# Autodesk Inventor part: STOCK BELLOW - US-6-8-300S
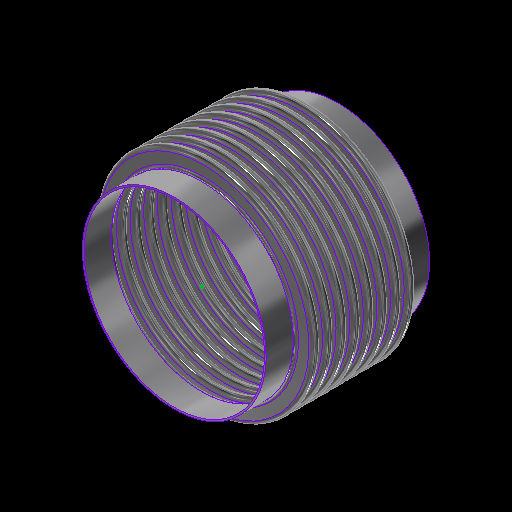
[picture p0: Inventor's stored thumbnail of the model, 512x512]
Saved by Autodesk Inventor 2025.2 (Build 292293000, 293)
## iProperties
Category: 22 GA (0.030 THICK)
RuleStatus: InUse
Created: 2024-01
Part Number: STOCK BELLOW - US-6-8-300S
Project: =STOCK BELLOWS: <Stock Number><SFILL>
Material: ASTM A240-304
Description: =STOCK BELLOWS: <Stock Number>, <SID_> I.D., <SOD_> O.D., <SPLY_> PLY, <Category>, <SNET_CONS> CONS.<PITCH_><STANGENT_> TANGENT<SFILL>
Document SubType Name: Sheet Metal
Designer: GS
Stock Number: U.S-6-8-300S
Surface Area: 4243.64 cm^2
Volume: 319.648 cm^3
Sheet Metal Rule: Default
Appearance: STAINLESS STEEL
Mass: 2575.5 g
Density: 8.05729 g/cm^3
THK: 0.036
ID: 3.500
OD: 4.250
CONS_: 2
PITCH: 0.500
TANGENT: 0.500
BELLOWS_UPSET: 0.000
d79: 1.000
d82: 1.000
d83: 26.000
d84: 24.000
d174: 8
d214: 8
STHK_: 0.030
SID_: 6.625
SOD_: 8.000
SPITCH_: 0.500
STANGENT__: 1.000
SBELLOWS_UPSET_: 0.000
SDIFF_TAN: 1.000
d252: 2
d275: 2
d287: 0.050
d289: 0.500
d290: 0.000
SOD_NECK: 6 3/4
PLY: 1
PSET: 4.178
PBAR: 1.035
COUNTER: 1.500
NET_TUBE: 3.071
CONS: 2
S_CONS: 0
NET_CONS: 2
ID_M: 88.90 mm
OD_M: 107.95 mm
THK_M: 0.91 mm
ID_U: 3.500 in
OD_U: 4.250 in
THK_U: 0.036 in
TANGENT2: 0.500
TAN_TO_TAN: 1.000 in
d80: 2.571
d81: 10
SID: 2.375
SCONS_: 8
SPITCH: 0.250
STANGENT_: 1.000
SBELLOWS_UPSET: 0.000
SNET_CONS: 8
SS_CONS: 0
SCONS: 8
d190: 8
d191: 1
d192: 1
d193: 8
d194: 0
SIZE: 6.00
PRESSURE: 300
d230: 8
STANGENT: 4.000
SPLY_: 2
d233: 8
d234: 0
d263: 2
d265: 1
d268: 2
d269: 0
d286: 2
d288: 1
d291: 2
d292: 0
SREROLL: 0.750
BLETP: 0.000 ul
PRES_Copy: 85
MATTABLE: 20 GA (0.036 THICK)
PART_NUMBER: U.S-6-8-300S
PITCH_: =, <SPITCH_> PITCH,
CFILL: .
SFILL: .
MESH: ,
COMP: 0.84
EXT: 0.42
LAT: 0.15
ANG: 573
ASR: 2809
LSR: 14080
ANSR: 328
PRES: 300
COMPM: 8.4
EXTM: 4.2
LATM: 1.50
ASRM: 491.940
PRESM: 20.684
LSRM: 2465.830
ANSRM: 57.443
TEMPMIN: 20
TEMPMAX: 800
TEMPMINM: -7
TEMPMAXM: 427
WEIGHTM: 2.575
WEIGHT: 5.678
Author: GS
Keywords: 20 GA (0.036 THICK)
Comments: =STOCK BELLOW - <STOCK NUMBER>
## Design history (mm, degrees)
sketch "Sketch2"
  geometry: L1 (0, -177.245)-(0, 562.856) reference; L2 (45.364, 0)-(44.45, 0); L3 (48.082, -2.718)-(50.343, -2.718); L4 (48.082, -3.632)-(50.343, -3.632); L5 (50.343, -9.982)-(48.082, -9.982); L6 (50.343, -9.068)-(48.082, -9.068); L7 (45.364, -12.7)-(44.45, -12.7); L8 (48.082, 0)-(48.082, -12.7); L9 (50.343, -6.35)-(53.975, -6.35); L10 (44.45, 0)-(44.45, -12.7); L11 (20.376, 102.841)-(20.376, 101.926); L12 (58.262, 457.127)-(58.262, 349.177); L13 (58.262, 444.427)-(58.262, 336.477); L14 (93.133, -58.817)-(93.133, -71.517); L15 (118.746, -66.401)-(118.746, -66.401); L16 (50.343, -9.068)-(50.343, -9.982); L17 (48.082, -9.068)-(48.082, -9.982); L18 (48.082, -9.525)-(50.343, -9.525); L19 (53.975, 0)-(53.975, -12.7); L20 (-50.343, -9.068)-(-50.343, -9.982); L21 (-50.343, -2.718)-(-48.082, -2.718); L22 (-50.343, -3.632)-(-48.082, -3.632); L23 (-48.082, -9.068)-(-50.343, -9.068); L24 (-50.343, -9.525)-(-48.082, -9.525); L25 (-48.082, -9.982)-(-50.343, -9.982); L26 (-48.082, -9.068)-(-48.082, -9.982); L27 (-44.45, 0.653)-(-44.45, -12.047); L28 (-48.082, -6.35)-(-44.45, -6.35); L29 (-50.343, 0.653)-(-50.343, -12.7); L30 (-53.061, 0)-(-53.975, 0); L31 (-53.975, 0)-(-53.975, -12.7); L32 (-53.061, -12.7)-(-53.975, -12.7); A1 r 2.718 centre (48.082, 0) between (45.364, 0) and (48.082, -2.718); A2 r 3.632 centre (48.082, 0) between (44.45, 0) and (48.082, -3.632); A3 r 3.632 centre (50.343, -6.35) between (50.343, -9.982) and (50.343, -2.718); A4 r 2.718 centre (50.343, -6.35) between (50.343, -9.068) and (50.343, -3.632); A5 r 2.718 centre (48.082, -12.7) between (48.082, -9.982) and (45.364, -12.7); A6 r 3.632 centre (48.082, -12.7) between (48.082, -9.068) and (44.45, -12.7); A7 r 3.175 centre (50.343, -6.35) between (50.343, -9.525) and (53.518, -6.35); A8 r 3.175 centre (48.082, -12.7) between (48.082, -9.525) and (44.907, -12.7); A9 r 2.718 centre (-50.343, -12.7) between (-50.343, -9.982) and (-53.061, -12.7); A10 r 2.718 centre (-48.082, -6.35) between (-48.082, -9.068) and (-48.082, -3.632); A11 r 3.175 centre (-48.082, -6.35) between (-48.082, -9.525) and (-44.907, -6.35); A12 r 3.632 centre (-48.082, -6.35) between (-48.082, -9.982) and (-48.082, -2.718); A13 r 3.175 centre (-50.343, -12.7) between (-50.343, -9.525) and (-53.518, -12.7); A14 r 3.632 centre (-50.343, -12.7) between (-50.343, -9.068) and (-53.975, -12.7); A15 r 2.718 centre (-50.343, 0) between (-53.061, 0) and (-50.343, -2.718); A16 r 3.632 centre (-50.343, 0) between (-53.975, 0) and (-50.343, -3.632); 10 further points
  constraints: 62 end point, 38 point on circle, 20 tangent, 16 centre point, 12 parallel, 9 midpoint, 7 vertical, 6 coincident, 6 concentric, 6 point on line, 4 equal radius, 4 perpendicular, 3 horizontal, 1 collinear, 1 horizontal alignment, 10 other
  dimensions: "THK" = 0.9144 distance of L11.start L11.end; "ID" = 88.9 distance of L11.end point (20.376, 13.026); "OD" = 107.95 distance of L12.start L12.end; "PITCH" = 12.7 distance of L12.start L13.start; "TANGENT" = 12.7 distance of L14.start L14.end; "BELLOWS_UPSET" = 0 distance of L15.start L15.end; "d43" = 88.9 diameter of L10 L1 (= ID); "d44" = 107.95 diameter of L9.end L1 (= OD); "d45" = 0.9144 distance between parallel lines of L5 L6 (computed from THK, PLY); "d46" = 3.6322 radius of A3 (computed from PITCH, THK, PLY); "UPSET_PITCH" = 12.7 distance of L2.end L7.end (derived); "SIDEWALL_ANGLE" = 360 deg dimension on L3 L9 (derived); "CON_GAP" = 5.4356 distance of point (48.082, -9.068) point (48.082, -3.632) (derived); "TAN1" = 4.98728 dimension on A8 (derived); "TAN2" = 4.98728 dimension on A7 (derived); "LEG1" = 2.2606 distance of L18.start L18.end (derived); "d278" = 0.9144 distance between parallel lines of L25 L23 (derived); "d279" = 3.6322 radius of A12 (derived); "d280" = 12.7 distance of L30.end L31.end (derived); "d281" = 360 deg dimension on L21 L28 (derived); "d282" = 5.4356 distance of point (-50.343, -9.068) point (-50.343, -3.632) (derived); "d283" = 4.98728 dimension on A13 (derived); "d284" = 4.98728 dimension on A11 (derived); "d285" = 2.2606 distance of L24.start L24.end (derived); "d293" = 88.9 diameter of L27 L1 (derived); "d294" = 107.95 diameter of L31 L1 (derived)
  node "Sketch Rectangular Pattern1" dims "d31" = 25.4, "ID" = 88.9
  node "Sketch Rectangular Pattern2" dims "d39" = 25.4, "PITCH" = 12.7
revolve "CONS" stored, may be unused: angle "d48" = 90 deg
node "BELLOW MIDPLANE"
pattern_linear "Rectangular Pattern2" dims "d52" = 12.7 (= UPSET_PITCH)
sketch "Sketch5"
  geometry: C1 r 45.364 at (0, 0) reference; C2 r 44.45 at (0, 0) reference
extrude "TANGENT" new body sketch "Sketch5" distance "d53" = 12.7 (= TANGENT); taper "d54" = 0 deg
revolve "SAMETAN" stored, may be unused: angle "d65" = 90 deg
revolve "DIFFTAN" stored, may be unused: angle "d70" = 90 deg
sketch "Sketch9"
  geometry: L1 (53.319, 0)-(-53.319, 0) reference; L2 (0, -17.78)-(0, 17.78) reference; L3 (38.085, 0)-(-38.085, 0); L4 (38.085, -11.906)-(38.085, 11.906); L5 (25.385, -11.906)-(25.385, 11.906); L6 (13.15, 11.906)-(13.15, -11.906); L7 (-25.385, -11.906)-(-25.385, 11.906); L8 (-38.085, -11.906)-(-38.085, 11.906); L9 (37.291, -11.906)-(37.291, 11.906); L10 (38.085, -11.906)-(37.291, -11.906); L11 (38.085, 11.906)-(37.291, 11.906); L12 (13.546, 11.906)-(12.753, 11.906); L13 (12.753, 11.906)-(12.753, -11.906); L14 (12.753, -11.906)-(13.546, -11.906); L15 (13.546, -11.906)-(13.546, 11.906); L16 (-13.546, 11.906)-(-13.546, -11.906); L17 (-13.15, 11.906)-(-13.15, -11.906); L18 (-13.546, -11.906)-(-12.753, -11.906); L19 (-12.753, -11.906)-(-12.753, 11.906); L20 (-12.753, 11.906)-(-13.546, 11.906); L21 (-38.085, -11.906)-(-37.291, -11.906); L22 (-37.291, -11.906)-(-37.291, 11.906); L23 (-37.291, 11.906)-(-38.085, 11.906); L24 (-38.085, 11.906)-(-38.085, -11.906); L25 (38.085, -0.397)-(-38.085, -0.397); L26 (-38.085, -0.397)-(-38.085, 0.397); L27 (-38.085, 0.397)-(38.085, 0.397); L28 (38.085, 0.397)-(38.085, -0.397); L29 (-38.085, 11.906)-(38.085, 11.906); L30 (38.085, 11.906)-(38.085, 12.7); L31 (38.085, 12.7)-(-38.085, 12.7); L32 (-38.085, 12.7)-(-38.085, 11.906); L33 (38.085, -11.906)-(-38.085, -11.906); L34 (-38.085, -11.906)-(-38.085, -12.7); L35 (-38.085, -12.7)-(38.085, -12.7); L36 (38.085, -12.7)-(38.085, -11.906); 30 further points
  constraints: 68 end point, 13 midpoint, 13 parallel, 8 horizontal, 7 perpendicular, 6 equal length, 3 point on line, 2 vertical, 14 other
  dimensions: "d115" = 23.8125 distance of L4.start L4.end (derived); "d116" = 12.7 distance between parallel lines of L4 L5 (derived); "d117" = 12.23516 distance between parallel lines of L5 L6 (derived); "d125" = 38.53427 distance between parallel lines of L7 L6 (derived); "d127" = 12.7 distance between parallel lines of L8 L7 (derived); "d128" = 24.93516 distance between parallel lines of L6 L4 (derived); "d130" = 76.16943 distance between parallel lines of L8 L4 (derived); "RULER_THK" = 0.79375 distance between parallel lines of L4 L9; "d135" = 0.79375 distance of L13.end L14.end (derived); "d138" = 26.29911 distance of L13.end L16.end (derived); "d143" = 0.79375 distance of L22.end L8.end (derived); "d144" = 0.79375 distance between parallel lines of L27 L25 (derived)
extrude "RULER" join sketch "Sketch9" distance "d149" = 0.79375 (derived); taper "d150" = 0 deg
extrude "BARS" join sketch "Sketch9" distance "d151" = 0.79375 (derived); taper "d152" = 0 deg
pattern_linear "Rectangular Pattern4" dims "d155" = 26.29911 (derived)
sketch "Sketch13"
  geometry: L1 (93.149, -52.467)-(93.149, -77.867); L2 (85.662, 0)-(84.138, 0); L3 (85.662, -12.7)-(84.138, -12.7); L4 (97.663, -10.287)-(88.075, -10.287); L5 (97.663, -8.763)-(88.075, -8.763); L6 (97.663, -6.35)-(101.6, -6.35); L7 (88.075, -2.413)-(97.663, -2.413); L8 (88.075, 0)-(88.075, -12.7); L9 (84.138, 0)-(84.138, -12.7); L10 (58.254, -293.231)-(58.254, -496.431); L11 (58.254, -305.931)-(58.254, -509.131); L12 (58.254, -331.331)-(58.254, -534.531); L13 (58.254, -344.031)-(58.254, -547.231); L14 (58.254, -356.731)-(58.254, -559.931); L15 (58.254, -369.431)-(58.254, -572.631); L16 (58.254, -382.131)-(58.254, -585.331); L17 (58.254, -318.631)-(58.254, -521.831); L18 (20.376, 102.688)-(20.376, 101.926); L19 (88.075, -3.937)-(97.663, -3.937); L20 (0, -722.935)-(0, 240.292) reference; L21 (-23.752, 0)-(142.514, 0) reference; A1 r 2.413 centre (88.075, 0) between (85.662, 0) and (88.075, -2.413); A2 r 2.413 centre (88.075, -12.7) between (88.075, -10.287) and (85.662, -12.7); A3 r 3.937 centre (88.075, -12.7) between (88.075, -8.763) and (84.138, -12.7); A4 r 2.413 centre (97.663, -6.35) between (97.663, -8.763) and (97.663, -3.937); A5 r 3.937 centre (97.663, -6.35) between (97.663, -10.287) and (97.663, -2.413); A6 r 3.937 centre (88.075, 0) between (84.138, 0) and (88.075, -3.937); 6 further points; 1 other entity
  constraints: 38 end point, 15 point on circle, 9 tangent, 6 centre point, 6 parallel, 5 vertical alignment, 4 point on line, 4 vertical, 3 coincident, 3 concentric, 2 collinear, 2 equal radius, 1 horizontal, 1 perpendicular, 23 other
  dimensions: "SBELLOWS_UPSET_" = 0 distance of point (118.762, -66.401) point (118.762, -66.401); "STOTAL_THK_BELLOW__" = 1.524 distance between parallel lines of L4 L5 (derived); "d224" = 3.937 radius of A5 (derived); "d225" = 12.7 distance of L2.end L3.end (derived); "SSIDEWALL_ANGLE_" = 0 deg angle of L7 L6 (derived); "SSCON_GAP_" = 4.826 distance of point (88.075, -8.763) point (88.075, -3.937) (derived); "d235" = 168.275 diameter of L9 L20 (derived); "d236" = 203.2 diameter of L6.end L20 (derived)
  node "Sketch Rectangular Pattern4" dims "d228" = 25.4
  node "Sketch Rectangular Pattern5" dims "d229" = 25.4
revolve "SBELLOW" stored, may be unused: angle "d197" = 90 deg
pattern_linear "Rectangular Pattern5" dims "d204" = 12.7 (derived)
revolve "STANGENT" stored, may be unused: angle "d240" = 90 deg
revolve "SSAMETAN" stored, may be unused: angle "d241" = 90 deg
revolve "SDIFFTAN" stored, may be unused: angle "d246" = 90 deg
revolve "INVCON" stored, may be unused: angle "d295" = 90 deg
pattern_linear "Rectangular Pattern6" dims "d298" = 12.7 (derived)
revolve "INVTANGENT" stored, may be unused: angle "d302" = 90 deg
revolve "INVSAMETAN" stored, may be unused: angle "d307" = 90 deg
revolve "INVDIFFTAN" stored, may be unused: angle "d312" = 90 deg
sketch "ID BELLOW MOUNT CALC"
  geometry: L1 (44.45, 0)-(38.1, 0); L2 (38.1, 0)-(38.1, 12.7); L3 (38.1, 12.7)-(44.45, 12.7); L4 (44.45, 12.7)-(44.45, 0); L5 (36.513, 12.7)-(35.598, 12.7); L6 (35.598, 12.7)-(35.598, 0); L7 (35.598, 0)-(36.513, 0); L8 (36.513, 0)-(36.513, 12.7); L9 (0, -2.54)-(0, 15.24) reference; L10 (-8.89, 0)-(53.34, 0) reference; 1 further point
  constraints: 16 end point, 5 parallel, 2 collinear, 2 horizontal, 2 perpendicular
  dimensions: "d314" = 12.7 distance of L5.end L6.end (derived); "d315" = 0.9144 distance of L5.start L5.end (derived); "IG" = 1.5875 distance between parallel lines of L2 L8; "PIPE_OD" = 88.9 diameter of L4 L9; "PIPE_WALL" = 6.35 distance of L2.end L3.end; "ID_MT_BELLOW" = 71.1962 diameter of L6 L9 (derived)
revolve "CFILL" stored, may be unused: angle "d320" = 90 deg
pattern_linear "Rectangular Pattern7" dims "d323" = 12.7 (derived)
revolve "SFILL" stored, may be unused: angle "d324" = 90 deg
pattern_linear "Rectangular Pattern8" dims "d327" = 12.7 (derived)
node "STOCK BELLOW MIDPLANE"
node "BELLOW"
sketch "Sketch6"
  geometry: L1 (-12.7, 45.364)-(0, 45.364); L2 (0, 45.364)-(0, 44.45); L3 (0, 44.45)-(-12.7, 44.45); L4 (-12.7, 44.45)-(-12.7, 45.364); L5 (10.16, 0)-(-60.96, 0) reference; L6 (-38.1, -89.422)-(-38.1, 153.44) reference; 1 further point
  constraints: 8 end point, 2 parallel, 1 horizontal, 1 perpendicular
  dimensions: "d61" = 12.7 distance of L2.end L3.end (derived); "d62" = 0.9144 distance of L1.end L2.end (derived); "d63" = 88.9 diameter of L3 L5 (derived); "d64" = 25.4 distance between parallel lines of L4 L6 (derived)
sketch "Sketch12"
  geometry: 1 further point
sketch "Sketch14"
  geometry: L1 (-25.4, 85.662)-(0, 85.662); L2 (0, 85.662)-(0, 84.138); L3 (0, 84.138)-(-25.4, 84.138); L4 (-25.4, 84.138)-(-25.4, 85.662); L5 (5.08, 0)-(-30.48, 0) reference; L6 (0, -17.132)-(0, 102.794) reference; 1 further point
  constraints: 8 end point, 2 parallel, 1 collinear, 1 horizontal, 1 perpendicular
  dimensions: "d237" = 1.524 distance of L3.end L1.start (derived); "d238" = 168.275 diameter of L3 L5 (derived); "d239" = 25.4 distance of L1.start L1.end (derived); "SOD_NECK" = 171.323 diameter of L1 L5 (derived)
sketch "Sketch15"
  geometry: L1 (-17.132, 0)-(102.794, 0) reference; L2 (84.138, -101.6)-(85.662, -101.6); L3 (85.662, -101.6)-(85.662, -127); L4 (85.662, -127)-(84.138, -127); L5 (84.138, -127)-(84.138, -101.6); L6 (0, -154.94)-(0, 40.64) reference; 1 further point
  constraints: 8 end point, 2 parallel, 1 horizontal, 1 perpendicular
  dimensions: "d205" = 25.4 distance of L4.end L2.start (derived); "d206" = 1.524 distance of L3.end L4.end (derived); "d207" = 168.275 diameter of L5 L6 (derived); "d208" = 101.6 distance between parallel lines of L1 L2 (derived)
node "TANGENT_"
node "SAME_TAN"
sketch "Sketch8"
  geometry: L1 (45.364, -25.4)-(44.45, -25.4); L2 (44.45, -25.4)-(44.45, -38.1); L3 (44.45, -38.1)-(45.364, -38.1); L4 (45.364, -38.1)-(45.364, -25.4); L5 (0, -48.26)-(0, 22.86) reference; L6 (-89.422, 0)-(153.44, 0) reference; 1 further point
  constraints: 8 end point, 2 parallel, 1 horizontal, 1 perpendicular
  dimensions: "d66" = 88.9 diameter of L2 L5 (derived); "TOTAL_THK_BELLOW" = 0.9144 distance of L2.end L3.end (derived); "d68" = 25.4 distance between parallel lines of L1 L6 (derived); "d69" = 12.7 distance of L1.end L2.end (derived)
node "DIFF_TAN"
node "Sketch Rectangular Pattern3" dims "d138" = 26.29911 (derived), "d141" = 25.4
node "SBELLOW_"
node "STANGENT_"
node "SSAME_TAN"
sketch "Sketch16"
  geometry: L1 (85.661, -101.6)-(84.138, -101.6); L2 (84.138, -101.6)-(84.138, -127); L3 (84.138, -127)-(85.662, -127); L4 (85.662, -127)-(85.661, -101.6); L5 (0, -154.94)-(0, 40.64) reference; L6 (-17.132, 0)-(102.794, 0) reference; 1 further point
  constraints: 8 end point, 2 parallel, 1 horizontal, 1 perpendicular
  dimensions: "SDIFF_TAN" = 25.4 distance of L3.end L1.start; "d243" = 1.524 distance of L2.end L3.end (derived); "d244" = 101.6 distance between parallel lines of L1 L6 (derived); "d245" = 168.275 diameter of L2 L5 (derived)
node "SDIFF_TAN"
body "Solid15"
sketch "Sketch17"
  geometry: L1 (53.975, 12.7)-(53.061, 12.7); L2 (53.061, 12.7)-(53.061, 0); L3 (53.061, 0)-(53.975, 0); L4 (53.975, 0)-(53.975, 12.7); L5 (0, -2.54)-(0, 15.24) reference; L6 (-10.795, 0)-(64.77, 0) reference; 2 further points
  constraints: 8 end point, 2 parallel, 1 horizontal, 1 midpoint, 1 perpendicular, 1 point on line
  dimensions: "INVTANGENT" = 12.7 distance of L3.end L1.start (derived); "d300" = 0.9144 distance of L1.start L1.end (derived); "d301" = 107.95 diameter of L4 L5 (derived)
body "Solid16"
sketch "Sketch18"
  geometry: L1 (53.975, -25.4)-(53.061, -25.4); L2 (53.061, -25.4)-(53.061, -38.1); L3 (53.061, -38.1)-(53.975, -38.1); L4 (53.975, -38.1)-(53.975, -25.4); L5 (-10.795, 0)-(64.77, 0) reference; L6 (0, -48.26)-(0, 22.86) reference; 1 further point
  constraints: 8 end point, 2 parallel, 1 horizontal, 1 perpendicular
  dimensions: "d303" = 25.4 distance between parallel lines of L1 L5 (derived); "d304" = 12.7 distance of L3.end L1.start (derived); "d305" = 0.9144 distance of L2.end L3.end (derived); "d306" = 107.95 diameter of L4 L6 (derived)
body "Solid17"
sketch "Sketch19"
  geometry: L1 (53.975, -25.4)-(53.061, -25.4); L2 (53.061, -25.4)-(53.061, -38.1); L3 (53.061, -38.1)-(53.975, -38.1); L4 (53.975, -38.1)-(53.975, -25.4); L5 (0, -48.26)-(0, 22.86) reference; L6 (-10.795, 0)-(64.77, 0) reference; 1 further point
  constraints: 8 end point, 2 parallel, 1 horizontal, 1 perpendicular
  dimensions: "d308" = 12.7 distance of L1.end L2.end (derived); "d309" = 107.95 diameter of L4 L5 (derived); "d310" = 0.9144 distance of L2.end L3.end (derived); "d311" = 25.4 distance between parallel lines of L1 L6 (derived)
body "Solid18"
body "Solid19"
body "Solid20"
other parameters: "BMPL" = -50.8, "PSET" = 106.1212 (computed from OD, THK, PLY) [user parameter], "PBAR" = 26.29911 (= 0.570796 x PITCH + OD - ID) [user parameter; used in 1 equation term], "COUNTER" = 15 [user parameter], "NET_TUBE" = 77.99823 (computed from CONS_, PBAR, TANGENT) [user parameter], "S_CONS" = 0 [user parameter; used in 1 equation term], "ID_M" = 88.9 (= ID) [user parameter], "OD_M" = 107.95 (= OD) [user parameter], "THK_M" = 0.9144 (= THK) [user parameter], "ID_U" = 88.9 (= ID) [user parameter], "OD_U" = 107.95 (= OD) [user parameter], "THK_U" = 0.9144 (= THK) [user parameter], "D_UNITS" = 0 [user parameter], "TANGENT2" = 12.7 [user parameter], "TAN_TO_TAN" = 25.4 [user parameter], "OD_NECK" = 90.7288 [user parameter], "d79" = 25.4, "d80" = 65.29823 [user parameter], "d82" = 25.4, "d83" = 660.4, "d84" = 609.6, "sa_0" = 4, "FRAME_THK" = 0.79375 [user parameter], "CON_FLAT" = 12.23516 [user parameter], "SID" = 60.325 [user parameter], "SPITCH" = 6.35 [user parameter], "STANGENT_" = 25.4 [user parameter], "SBELLOWS_UPSET" = 0 [user parameter], "SS_CONS" = 0 [user parameter], "STAN_TO_TAN_" = 101.6 [user parameter], "d100" = 1.524 [user parameter], "d191" = 25.4 [user parameter], "d194" = 0 [user parameter], "STANGENT" = 101.6 [user parameter], "d234" = 0 [user parameter], "SUPSET_PITCH_" = 12.7 [user parameter], "d269" = 0 [user parameter], "d287" = 1.27, "d289" = 12.7, "d290" = 0, "d292" = 0 [user parameter], "Thickness" = 3.048 (derived), "KFactor" = 4.4, "BendRadius" = 3.048 (derived), "BendReliefWidth" = 3.048 (derived), "BendReliefDepth" = 1.524 (derived), "CornerReliefSize" = 12.192 (derived), "SeamGap" = 0.00508, "MinimumRemnant" = 6.096 (derived), "TransitionRadius" = 3.048 (derived), "JacobiRadiusSize" = 3.048 (derived), "GapSize" = 3.048 (derived), "SREROLL" = 19.05 [user parameter], "CUR_STK_PITCH" = 12.7 [user parameter], "d328" = -50.8 (derived), "ASR" = 28090 [user parameter], "LSR" = 140800 [user parameter], "BLETP" = 0 [user parameter], "ASRM" = 4919.4017 [user parameter], "PRESM" = 206.83949 [user parameter], "LSRM" = 24658.304 [user parameter], "ANSRM" = 574.4264 [user parameter], "TEMPMIN" = 2664.83333 [user parameter], "TEMPMAX" = 6998.16667 [user parameter], "TEMPMINM" = 2664.83333 [user parameter], "TEMPMAXM" = 6998.16667 [user parameter], "WEIGHT" = 25.75499 [user parameter], "WEIGHTM" = 0.02575 [user parameter]
